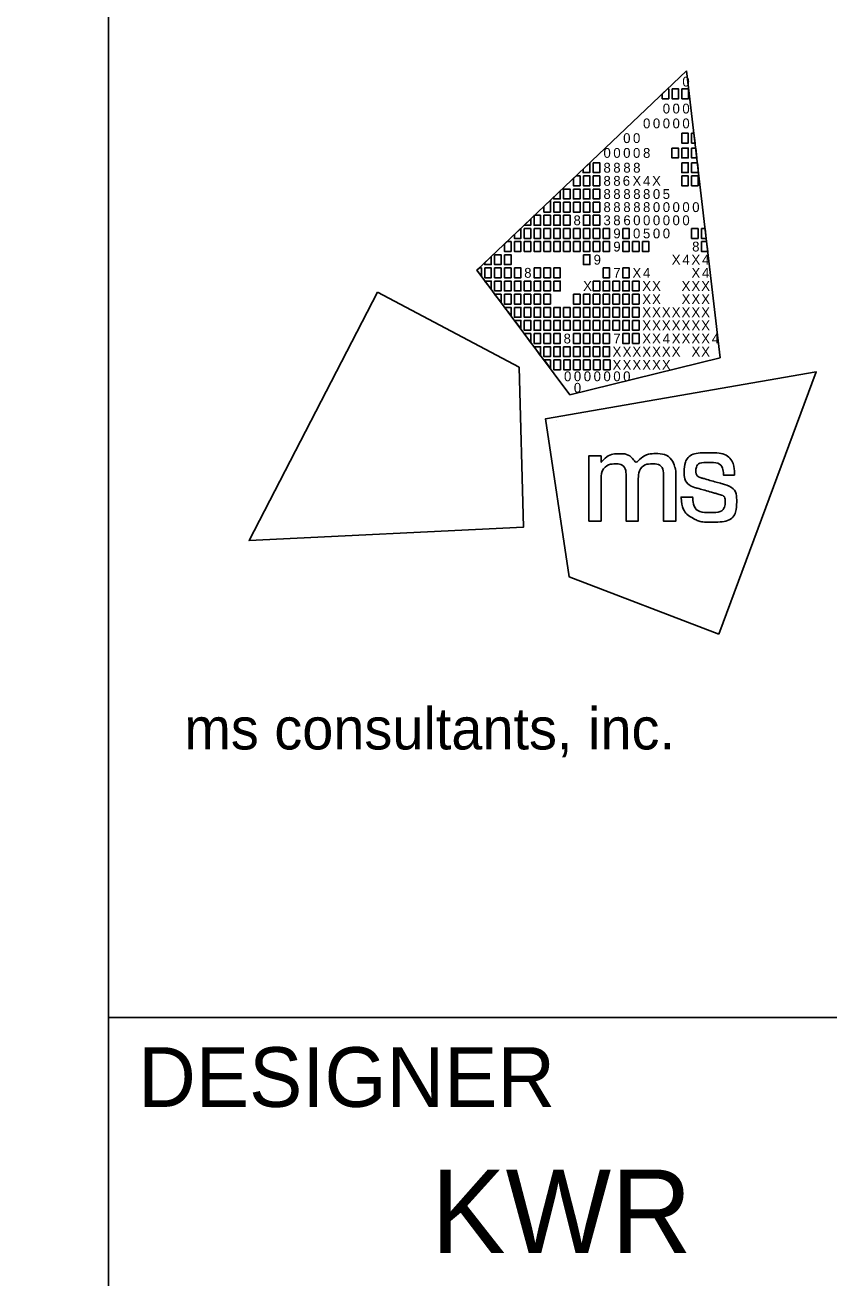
# Model space of a CAD drawing. Extents: x -0.2 to 34, y 0 to 22.
# Drawn here: x 31.86 to 33.207, y 2.063 to 4.163 of the extents above; entities that cross this region are included whole.
import ezdxf

# ---------------------------------------------------------------- set-up
doc = ezdxf.new("R2010")
doc.units = 0
for name, color, linetype in [('SC_Scratch1', 7, 'Continuous'), ('SH_Border', 7, 'Continuous'), ('SH_Data', 7, 'Continuous')]:
    doc.layers.add(name, color=color, linetype=linetype)

msp = doc.modelspace()

# ---------------------------------------------------------------- linework, layer by layer
at = {"layer": 'SC_Scratch1'}
msp.add_lwpolyline([(1.5, 21.5), (32, 21.5), (32, 0.5), (1.5, 0.5)], close=True, dxfattribs=at)
at = {"layer": 'SH_Border'}
for p, q in [((32, 0.5), (32, 21.5)), ((32, 2.5), (33.5, 2.5))]:
    msp.add_line(p, q, dxfattribs=at)
at = {"layer": 'SH_Data'}
for p, q in [((32.6175, 3.7519), (32.9688, 4.0861)), ((32.9688, 4.0861), (32.9688, 4.0861)), ((32.9688, 4.0861), (33.0253, 3.6052)), ((32.773, 3.543), (32.6175, 3.7519)), ((33.0253, 3.6052), (32.773, 3.543)), ((32.75, 3.5), (32.75, 3.5))]:
    msp.add_line(p, q, dxfattribs=at)
for points in [[(32.9279, 4.0472), (32.9369, 4.0558), (32.9389, 4.0558), (32.9389, 4.0393), (32.9279, 4.0393)], [(32.9444, 4.0558), (32.9554, 4.0558), (32.9554, 4.0393), (32.9444, 4.0393)], [(32.9609, 4.0558), (32.9719, 4.0558), (32.9719, 4.0393), (32.9609, 4.0393)], [(32.9606, 3.9815), (32.9716, 3.9815), (32.9716, 3.965), (32.9606, 3.965)], [(32.9771, 3.9815), (32.9811, 3.9815), (32.983, 3.965), (32.9771, 3.965)], [(32.9441, 3.9567), (32.9551, 3.9567), (32.9551, 3.9402), (32.9441, 3.9402)], [(32.9606, 3.9567), (32.9716, 3.9567), (32.9716, 3.9402), (32.9606, 3.9402)], [(32.9771, 3.9567), (32.984, 3.9567), (32.9859, 3.9402), (32.9771, 3.9402)], [(32.7953, 3.9211), (32.8064, 3.9316), (32.8064, 3.9154), (32.7953, 3.9154)], [(32.8123, 3.9319), (32.8233, 3.9319), (32.8233, 3.9154), (32.8123, 3.9154)], [(32.9606, 3.9319), (32.9716, 3.9319), (32.9716, 3.9154), (32.9606, 3.9154)], [(32.9771, 3.9319), (32.9869, 3.9319), (32.9881, 3.9218), (32.9881, 3.9154), (32.9771, 3.9154)], [(32.7958, 3.9099), (32.8068, 3.9099), (32.8068, 3.8934), (32.7958, 3.8934)], [(32.8123, 3.9099), (32.8233, 3.9099), (32.8233, 3.8934), (32.8123, 3.8934)], [(32.9606, 3.9099), (32.9716, 3.9099), (32.9716, 3.8934), (32.9606, 3.8934)], [(32.9771, 3.9099), (32.9881, 3.9099), (32.9881, 3.8934), (32.9771, 3.8934)], [(32.7627, 3.8879), (32.7737, 3.8879), (32.7737, 3.8714), (32.7627, 3.8714)], [(32.7793, 3.8879), (32.7903, 3.8879), (32.7903, 3.8714), (32.7793, 3.8714)], [(32.7958, 3.8879), (32.8068, 3.8879), (32.8068, 3.8714), (32.7958, 3.8714)], [(32.8123, 3.8879), (32.8233, 3.8879), (32.8233, 3.8714), (32.8123, 3.8714)], [(32.7462, 3.8659), (32.7572, 3.8659), (32.7572, 3.8494), (32.7462, 3.8494)], [(32.7627, 3.8659), (32.7737, 3.8659), (32.7737, 3.8494), (32.7627, 3.8494)], [(32.7793, 3.8659), (32.7903, 3.8659), (32.7903, 3.8494), (32.7793, 3.8494)], [(32.7958, 3.8659), (32.8068, 3.8659), (32.8068, 3.8494), (32.7958, 3.8494)], [(32.8123, 3.8659), (32.8233, 3.8659), (32.8233, 3.8494), (32.8123, 3.8494)], [(32.7297, 3.8439), (32.7407, 3.8439), (32.7407, 3.8273), (32.7297, 3.8273)], [(32.7462, 3.8439), (32.7572, 3.8439), (32.7572, 3.8273), (32.7462, 3.8273)], [(32.7627, 3.8439), (32.7737, 3.8439), (32.7737, 3.8273), (32.7627, 3.8273)], [(32.7958, 3.8439), (32.8068, 3.8439), (32.8068, 3.8273), (32.7958, 3.8273)], [(32.8123, 3.8439), (32.8233, 3.8439), (32.8233, 3.8273), (32.8123, 3.8273)], [(32.6967, 3.8218), (32.7077, 3.8218), (32.7077, 3.8053), (32.6967, 3.8053)], [(32.7132, 3.8218), (32.7242, 3.8218), (32.7242, 3.8053), (32.7132, 3.8053)], [(32.7297, 3.8218), (32.7407, 3.8218), (32.7407, 3.8053), (32.7297, 3.8053)], [(32.7462, 3.8218), (32.7572, 3.8218), (32.7572, 3.8053), (32.7462, 3.8053)], [(32.7627, 3.8218), (32.7737, 3.8218), (32.7737, 3.8053), (32.7627, 3.8053)], [(32.7793, 3.8218), (32.7903, 3.8218), (32.7903, 3.8053), (32.7793, 3.8053)], [(32.7958, 3.8218), (32.8068, 3.8218), (32.8068, 3.8053), (32.7958, 3.8053)], [(32.8123, 3.8218), (32.8233, 3.8218), (32.8233, 3.8053), (32.8123, 3.8053)], [(32.8288, 3.8218), (32.8398, 3.8218), (32.8398, 3.8053), (32.8288, 3.8053)], [(32.8618, 3.8218), (32.8728, 3.8218), (32.8728, 3.8053), (32.8618, 3.8053)], [(32.9771, 3.8218), (32.9881, 3.8218), (32.9881, 3.8053), (32.9771, 3.8053)], [(32.9935, 3.8218), (32.9998, 3.8218), (33.0018, 3.8053), (32.9935, 3.8053)], [(32.6802, 3.7998), (32.6912, 3.7998), (32.6912, 3.7833), (32.6802, 3.7833)], [(32.6967, 3.7998), (32.7077, 3.7998), (32.7077, 3.7833), (32.6967, 3.7833)], [(32.7132, 3.7998), (32.7242, 3.7998), (32.7242, 3.7833), (32.7132, 3.7833)], [(32.7297, 3.7998), (32.7407, 3.7998), (32.7407, 3.7833), (32.7297, 3.7833)], [(32.7462, 3.7998), (32.7572, 3.7998), (32.7572, 3.7833), (32.7462, 3.7833)], [(32.7627, 3.7998), (32.7737, 3.7998), (32.7737, 3.7833), (32.7627, 3.7833)], [(32.7793, 3.7998), (32.7903, 3.7998), (32.7903, 3.7833), (32.7793, 3.7833)], [(32.7958, 3.7998), (32.8068, 3.7998), (32.8068, 3.7833), (32.7958, 3.7833)], [(32.8123, 3.7998), (32.8233, 3.7998), (32.8233, 3.7833), (32.8123, 3.7833)], [(32.8288, 3.7998), (32.8398, 3.7998), (32.8398, 3.7833), (32.8288, 3.7833)], [(32.8618, 3.7998), (32.8728, 3.7998), (32.8728, 3.7833), (32.8618, 3.7833)], [(32.8783, 3.7998), (32.8893, 3.7998), (32.8893, 3.7833), (32.8783, 3.7833)], [(32.8947, 3.7998), (32.9057, 3.7998), (32.9057, 3.7833), (32.8947, 3.7833)], [(32.9935, 3.7998), (33.0024, 3.7998), (33.0044, 3.7833), (32.9935, 3.7833)], [(32.6471, 3.7778), (32.6581, 3.7778), (32.6581, 3.7613), (32.6471, 3.7613)], [(32.6637, 3.7778), (32.6747, 3.7778), (32.6747, 3.7613), (32.6637, 3.7613)], [(32.7958, 3.7778), (32.8068, 3.7778), (32.8068, 3.7613), (32.7958, 3.7613)], [(32.6306, 3.7558), (32.6416, 3.7558), (32.6416, 3.7393), (32.6306, 3.7393)], [(32.6471, 3.7558), (32.6581, 3.7558), (32.6581, 3.7393), (32.6471, 3.7393)], [(32.6637, 3.7558), (32.6747, 3.7558), (32.6747, 3.7393), (32.6637, 3.7393)], [(32.6802, 3.7558), (32.6912, 3.7558), (32.6912, 3.7393), (32.6802, 3.7393)], [(32.7132, 3.7558), (32.7242, 3.7558), (32.7242, 3.7393), (32.7132, 3.7393)], [(32.7297, 3.7558), (32.7407, 3.7558), (32.7407, 3.7393), (32.7297, 3.7393)], [(32.7462, 3.7558), (32.7572, 3.7558), (32.7572, 3.7393), (32.7462, 3.7393)], [(32.8288, 3.7558), (32.8398, 3.7558), (32.8398, 3.7393), (32.8288, 3.7393)], [(32.8618, 3.7558), (32.8728, 3.7558), (32.8728, 3.7393), (32.8618, 3.7393)], [(32.6306, 3.7338), (32.6416, 3.7338), (32.6416, 3.72)], [(32.6471, 3.7338), (32.6581, 3.7338), (32.6581, 3.7173), (32.6471, 3.7173)], [(32.6637, 3.7338), (32.6747, 3.7338), (32.6747, 3.7173), (32.6637, 3.7173)], [(32.6802, 3.7338), (32.6912, 3.7338), (32.6912, 3.7173), (32.6802, 3.7173)], [(32.6967, 3.7338), (32.7077, 3.7338), (32.7077, 3.7173), (32.6967, 3.7173)], [(32.7132, 3.7338), (32.7242, 3.7338), (32.7242, 3.7173), (32.7132, 3.7173)], [(32.7297, 3.7338), (32.7407, 3.7338), (32.7407, 3.7173), (32.7297, 3.7173)], [(32.7462, 3.7338), (32.7572, 3.7338), (32.7572, 3.7173), (32.7462, 3.7173)], [(32.8123, 3.7338), (32.8233, 3.7338), (32.8233, 3.7173), (32.8123, 3.7173)], [(32.8288, 3.7338), (32.8398, 3.7338), (32.8398, 3.7173), (32.8288, 3.7173)], [(32.8453, 3.7338), (32.8563, 3.7338), (32.8563, 3.7173), (32.8453, 3.7173)], [(32.8618, 3.7338), (32.8728, 3.7338), (32.8728, 3.7173), (32.8618, 3.7173)], [(32.8783, 3.7338), (32.8893, 3.7338), (32.8893, 3.7173), (32.8783, 3.7173)], [(32.6471, 3.7117), (32.6581, 3.7117), (32.6581, 3.698)], [(32.6637, 3.7117), (32.6747, 3.7117), (32.6747, 3.6952), (32.6637, 3.6952)], [(32.6802, 3.7117), (32.6912, 3.7117), (32.6912, 3.6952), (32.6802, 3.6952)], [(32.6967, 3.7117), (32.7077, 3.7117), (32.7077, 3.6952), (32.6967, 3.6952)], [(32.7132, 3.7117), (32.7242, 3.7117), (32.7242, 3.6952), (32.7132, 3.6952)], [(32.7297, 3.7117), (32.7407, 3.7117), (32.7407, 3.6952), (32.7297, 3.6952)], [(32.7793, 3.7117), (32.7903, 3.7117), (32.7903, 3.6952), (32.7793, 3.6952)], [(32.7958, 3.7117), (32.8068, 3.7117), (32.8068, 3.6952), (32.7958, 3.6952)], [(32.8123, 3.7117), (32.8233, 3.7117), (32.8233, 3.6952), (32.8123, 3.6952)], [(32.8288, 3.7117), (32.8398, 3.7117), (32.8398, 3.6952), (32.8288, 3.6952)], [(32.8453, 3.7117), (32.8563, 3.7117), (32.8563, 3.6952), (32.8453, 3.6952)], [(32.8618, 3.7117), (32.8728, 3.7117), (32.8728, 3.6952), (32.8618, 3.6952)], [(32.8783, 3.7117), (32.8893, 3.7117), (32.8893, 3.6952), (32.8783, 3.6952)], [(32.6637, 3.6897), (32.6747, 3.6897), (32.6747, 3.676)], [(32.6747, 3.6897), (32.6747, 3.6897), (32.6747, 3.6897)], [(32.6802, 3.6897), (32.6912, 3.6897), (32.6912, 3.6732), (32.6802, 3.6732)], [(32.6967, 3.6897), (32.7077, 3.6897), (32.7077, 3.6732), (32.6967, 3.6732)], [(32.7132, 3.6897), (32.7242, 3.6897), (32.7242, 3.6732), (32.7132, 3.6732)], [(32.7297, 3.6897), (32.7407, 3.6897), (32.7407, 3.6732), (32.7297, 3.6732)], [(32.7462, 3.6897), (32.7572, 3.6897), (32.7572, 3.6732), (32.7462, 3.6732)], [(32.7627, 3.6897), (32.7737, 3.6897), (32.7737, 3.6732), (32.7627, 3.6732)], [(32.7793, 3.6897), (32.7903, 3.6897), (32.7903, 3.6732), (32.7793, 3.6732)], [(32.7958, 3.6897), (32.8068, 3.6897), (32.8068, 3.6732), (32.7958, 3.6732)], [(32.8123, 3.6897), (32.8233, 3.6897), (32.8233, 3.6732), (32.8123, 3.6732)], [(32.8288, 3.6897), (32.8398, 3.6897), (32.8398, 3.6732), (32.8288, 3.6732)], [(32.8453, 3.6897), (32.8563, 3.6897), (32.8563, 3.6732), (32.8453, 3.6732)], [(32.8618, 3.6897), (32.8728, 3.6897), (32.8728, 3.6732), (32.8618, 3.6732)], [(32.8783, 3.6897), (32.8893, 3.6897), (32.8893, 3.6732), (32.8783, 3.6732)], [(32.6802, 3.6677), (32.6912, 3.6677), (32.6912, 3.654)], [(32.6967, 3.6677), (32.7077, 3.6677), (32.7077, 3.6512), (32.6967, 3.6512)], [(32.7132, 3.6677), (32.7242, 3.6677), (32.7242, 3.6512), (32.7132, 3.6512)], [(32.7297, 3.6677), (32.7407, 3.6677), (32.7407, 3.6512), (32.7297, 3.6512)], [(32.7462, 3.6677), (32.7572, 3.6677), (32.7572, 3.6512), (32.7462, 3.6512)], [(32.7627, 3.6677), (32.7737, 3.6677), (32.7737, 3.6512), (32.7627, 3.6512)], [(32.7793, 3.6677), (32.7903, 3.6677), (32.7903, 3.6512), (32.7793, 3.6512)], [(32.7958, 3.6677), (32.8068, 3.6677), (32.8068, 3.6512), (32.7958, 3.6512)], [(32.8123, 3.6677), (32.8233, 3.6677), (32.8233, 3.6512), (32.8123, 3.6512)], [(32.8288, 3.6677), (32.8398, 3.6677), (32.8398, 3.6512), (32.8288, 3.6512)], [(32.8453, 3.6677), (32.8563, 3.6677), (32.8563, 3.6512), (32.8453, 3.6512)], [(32.8618, 3.6677), (32.8728, 3.6677), (32.8728, 3.6512), (32.8618, 3.6512)], [(32.8783, 3.6677), (32.8893, 3.6677), (32.8893, 3.6512), (32.8783, 3.6512)], [(32.7077, 3.6305), (32.6965, 3.6457), (32.7077, 3.6457)], [(32.7132, 3.6457), (32.7242, 3.6457), (32.7242, 3.6292), (32.7132, 3.6292)], [(32.7297, 3.6457), (32.7407, 3.6457), (32.7407, 3.6292), (32.7297, 3.6292)], [(32.7462, 3.6457), (32.7572, 3.6457), (32.7572, 3.6292), (32.7462, 3.6292)], [(32.7793, 3.6457), (32.7903, 3.6457), (32.7903, 3.6292), (32.7793, 3.6292)], [(32.7958, 3.6457), (32.8068, 3.6457), (32.8068, 3.6292), (32.7958, 3.6292)], [(32.8123, 3.6457), (32.8233, 3.6457), (32.8233, 3.6292), (32.8123, 3.6292)], [(32.8288, 3.6457), (32.8398, 3.6457), (32.8398, 3.6292), (32.8288, 3.6292)], [(32.8618, 3.6457), (32.8728, 3.6457), (32.8728, 3.6292), (32.8618, 3.6292)], [(32.8783, 3.6457), (32.8893, 3.6457), (32.8893, 3.6292), (32.8783, 3.6292)], [(32.724, 3.6082), (32.7132, 3.6237), (32.7242, 3.6237)], [(32.7297, 3.6237), (32.7407, 3.6237), (32.7407, 3.6072), (32.7297, 3.6072)], [(32.7462, 3.6237), (32.7572, 3.6237), (32.7572, 3.6072), (32.7462, 3.6072)], [(32.7627, 3.6237), (32.7737, 3.6237), (32.7737, 3.6072), (32.7627, 3.6072)], [(32.7793, 3.6237), (32.7903, 3.6237), (32.7903, 3.6072), (32.7793, 3.6072)], [(32.7958, 3.6237), (32.8068, 3.6237), (32.8068, 3.6072), (32.7958, 3.6072)], [(32.8123, 3.6237), (32.8233, 3.6237), (32.8233, 3.6072), (32.8123, 3.6072)], [(32.8288, 3.6237), (32.8398, 3.6237), (32.8398, 3.6072), (32.8288, 3.6072)], [(32.7302, 3.6017), (32.7407, 3.6017), (32.7408, 3.5875)], [(32.7463, 3.6017), (32.7573, 3.6017), (32.7573, 3.5852), (32.7463, 3.5852)], [(32.763, 3.6017), (32.774, 3.6017), (32.774, 3.5852), (32.763, 3.5852)], [(32.7794, 3.6017), (32.7904, 3.6017), (32.7904, 3.5852), (32.7794, 3.5852)], [(32.796, 3.6017), (32.807, 3.6017), (32.807, 3.5852), (32.796, 3.5852)], [(32.8129, 3.6017), (32.8239, 3.6017), (32.8239, 3.5851), (32.8129, 3.5851)], [(32.8296, 3.6017), (32.8406, 3.6017), (32.8406, 3.5851), (32.8296, 3.5851)]]:
    msp.add_lwpolyline(points, close=True, dxfattribs=at)
for points in [[(32.7903, 3.9099), (32.7836, 3.9099), (32.7793, 3.9058), (32.7793, 3.8934), (32.7903, 3.8934), (32.7903, 3.9099)], [(32.7572, 3.8849), (32.7462, 3.8744), (32.7462, 3.8714), (32.7572, 3.8714), (32.7572, 3.8849)], [(32.7407, 3.8691), (32.7297, 3.8587), (32.7297, 3.8494), (32.7407, 3.8494), (32.7407, 3.8691)], [(32.7242, 3.8439), (32.7141, 3.8439), (32.7132, 3.843), (32.7132, 3.8273), (32.7242, 3.8273), (32.7242, 3.8439)], [(32.6912, 3.822), (32.6802, 3.8115), (32.6802, 3.8053), (32.6912, 3.8053), (32.6912, 3.822)], [(32.7077, 3.8377), (32.6968, 3.8273), (32.7077, 3.8273), (32.7077, 3.8377)], [(32.6747, 3.7998), (32.6679, 3.7998), (32.6637, 3.7958), (32.6637, 3.7833), (32.6747, 3.7833), (32.6747, 3.7998)], [(32.6416, 3.7749), (32.6306, 3.7644), (32.6306, 3.7613), (32.6416, 3.7613), (32.6416, 3.7749)], [(32.6251, 3.7558), (32.6216, 3.7558), (32.6175, 3.7519), (32.6251, 3.7417), (32.6251, 3.7558)], [(32.4512, 3.7149), (32.2359, 3.2988), (32.6956, 3.3215), (32.6884, 3.5892), (32.4512, 3.7149)], [(33.0229, 3.1422), (33.1859, 3.5814), (32.7324, 3.5029), (32.7722, 3.2381), (33.0229, 3.1422)]]:
    msp.add_lwpolyline(points, dxfattribs=at)
for points in [[(32.8048, 3.3315), (32.8048, 3.3315), (32.8048, 3.4409), (32.8048, 3.4409), (32.8048, 3.4409), (32.8255, 3.4409), (32.8255, 3.4409), (32.8255, 3.4409), (32.8255, 3.4297), (32.8255, 3.4297), (32.8346, 3.4399), (32.8457, 3.4445), (32.8555, 3.4445), (32.8688, 3.4445), (32.8791, 3.4372), (32.8837, 3.4266), (32.8915, 3.4381), (32.905, 3.4446), (32.9166, 3.4446), (32.9325, 3.4446), (32.9451, 3.435), (32.9494, 3.4213), (32.9494, 3.4212), (32.9494, 3.4212), (32.9494, 3.4212), (32.9501, 3.419), (32.9506, 3.4172), (32.9506, 3.4071), (32.9506, 3.4071), (32.9506, 3.3314), (32.9506, 3.3314), (32.9506, 3.3314), (32.9303, 3.3314), (32.9303, 3.3314), (32.9303, 3.3314), (32.9303, 3.4048), (32.9303, 3.4048), (32.9303, 3.4201), (32.9219, 3.4274), (32.911, 3.4274), (32.8995, 3.4274), (32.8879, 3.4171), (32.8879, 3.4001), (32.8879, 3.4001), (32.8879, 3.3315), (32.8879, 3.3315), (32.8879, 3.3315), (32.8674, 3.3315), (32.8674, 3.3315), (32.8674, 3.3315), (32.8674, 3.4059), (32.8674, 3.4059), (32.8674, 3.4203), (32.8588, 3.4274), (32.8496, 3.4274), (32.8384, 3.4274), (32.8254, 3.417), (32.8254, 3.3962), (32.8254, 3.3962), (32.8254, 3.3315), (32.8254, 3.3315), (32.8254, 3.3315), (32.8048, 3.3315), (32.8048, 3.3315)], [(32.9595, 3.3709), (32.9595, 3.3709), (32.9595, 3.3717), (32.9595, 3.3717), (32.9595, 3.3717), (32.9603, 3.3717), (32.9603, 3.3717), (32.9603, 3.3717), (32.9783, 3.3717), (32.9783, 3.3717), (32.9783, 3.3717), (32.9789, 3.3717), (32.9789, 3.3717), (32.9789, 3.3717), (32.979, 3.371), (32.979, 3.371), (32.9803, 3.3554), (32.9887, 3.346), (33.009, 3.346), (33.0273, 3.346), (33.0333, 3.3554), (33.0333, 3.3631), (33.0333, 3.3732), (33.0256, 3.3758), (33.0175, 3.378), (33.0175, 3.378), (32.987, 3.3867), (32.987, 3.3867), (32.972, 3.3909), (32.9648, 3.4019), (32.9648, 3.4142), (32.9648, 3.4303), (32.9768, 3.4462), (33.0052, 3.4462), (33.0348, 3.4462), (33.0489, 3.4285), (33.0489, 3.4095), (33.0489, 3.4095), (33.0489, 3.4087), (33.0489, 3.4087), (33.0489, 3.4087), (33.0482, 3.4087), (33.0482, 3.4087), (33.0482, 3.4087), (33.0312, 3.4087), (33.0312, 3.4087), (33.0312, 3.4087), (33.0305, 3.4087), (33.0305, 3.4087), (33.0305, 3.4087), (33.0305, 3.4094), (33.0305, 3.4094), (33.0301, 3.4208), (33.0226, 3.43), (33.0056, 3.43), (32.9891, 3.43), (32.9843, 3.4218), (32.9843, 3.4157), (32.9843, 3.4108), (32.9869, 3.4059), (32.9959, 3.4033), (32.9959, 3.4033), (33.0255, 3.3948), (33.0255, 3.3948), (33.0462, 3.3889), (33.0527, 3.3777), (33.0527, 3.3639), (33.0527, 3.3462), (33.041, 3.3298), (33.0087, 3.3298), (32.9952, 3.3298), (32.9877, 3.3321), (32.9823, 3.3348), (32.969, 3.3414), (32.9609, 3.3536), (32.9595, 3.3709)]]:
    msp.add_open_spline(points, degree=3, dxfattribs=at)

# ---------------------------------------------------------------- texts
for s, height, p in [('0', 0.0165, (32.9617, 4.0597)), ('0', 0.0165, (32.9288, 4.0145)), ('0', 0.0165, (32.9452, 4.0145)), ('0', 0.0165, (32.9617, 4.0145)), ('0', 0.0165, (32.8958, 3.9897)), ('0', 0.0165, (32.9123, 3.9897)), ('0', 0.0165, (32.9288, 3.9897)), ('0', 0.0165, (32.9452, 3.9897)), ('0', 0.0165, (32.9617, 3.9897)), ('0', 0.0165, (32.8625, 3.965)), ('0', 0.0165, (32.879, 3.965)), ('0', 0.0165, (32.8295, 3.9402)), ('0', 0.0165, (32.846, 3.9402)), ('0', 0.0165, (32.8625, 3.9402)), ('0', 0.0165, (32.879, 3.9402)), ('8', 0.0165, (32.8958, 3.9402)), ('8', 0.0165, (32.8295, 3.9154)), ('8', 0.0165, (32.846, 3.9154)), ('8', 0.0165, (32.8628, 3.9154)), ('8', 0.0165, (32.8793, 3.9154)), ('8', 0.0165, (32.8295, 3.8934)), ('8', 0.0165, (32.846, 3.8934)), ('6', 0.0165, (32.8618, 3.8934)), ('X', 0.0165, (32.8781, 3.8934)), ('4', 0.0165, (32.8958, 3.8934)), ('X', 0.0165, (32.911, 3.8934)), ('8', 0.0165, (32.8295, 3.8713)), ('8', 0.0165, (32.846, 3.8713)), ('8', 0.0165, (32.8628, 3.8713)), ('8', 0.0165, (32.8794, 3.8713)), ('8', 0.0165, (32.8958, 3.8713)), ('0', 0.0165, (32.9123, 3.8713)), ('5', 0.0165, (32.9287, 3.8713)), ('8', 0.0165, (32.8295, 3.8494)), ('8', 0.0165, (32.846, 3.8494)), ('8', 0.0165, (32.8628, 3.8494)), ('8', 0.0165, (32.8794, 3.8494)), ('8', 0.0165, (32.8958, 3.8494)), ('0', 0.0165, (32.9123, 3.8494)), ('0', 0.0165, (32.9288, 3.8494)), ('0', 0.0165, (32.9452, 3.8494)), ('0', 0.0165, (32.9617, 3.8494)), ('0', 0.0165, (32.9782, 3.8494)), ('8', 0.0165, (32.7793, 3.8273)), ('3', 0.0165, (32.8295, 3.8273)), ('8', 0.0165, (32.846, 3.8273)), ('6', 0.0165, (32.8629, 3.8273)), ('0', 0.0165, (32.8793, 3.8273)), ('0', 0.0165, (32.8958, 3.8273)), ('0', 0.0165, (32.9123, 3.8273)), ('0', 0.0165, (32.9288, 3.8273)), ('0', 0.0165, (32.9452, 3.8273)), ('0', 0.0165, (32.9617, 3.8273)), ('9', 0.0165, (32.846, 3.8053)), ('0', 0.0165, (32.879, 3.8053)), ('5', 0.0165, (32.8957, 3.8053)), ('0', 0.0165, (32.9123, 3.8053)), ('0', 0.0165, (32.9288, 3.8053)), ('9', 0.0165, (32.846, 3.7833)), ('8', 0.0165, (32.9781, 3.7833)), ('9', 0.0165, (32.813, 3.7613)), ('X', 0.0165, (32.9439, 3.7613)), ('4', 0.0165, (32.9617, 3.7613)), ('X', 0.0165, (32.9769, 3.7613)), ('4', 0.0165, (32.9946, 3.7613)), ('8', 0.0165, (32.6967, 3.7393)), ('7', 0.0165, (32.846, 3.7393)), ('X', 0.0165, (32.8781, 3.7393)), ('4', 0.0165, (32.8958, 3.7393)), ('X', 0.0165, (32.9769, 3.7393)), ('4', 0.0165, (32.9946, 3.7393)), ('X', 0.0165, (32.7955, 3.7173)), ('X', 0.0165, (32.8945, 3.7173)), ('X', 0.0165, (32.911, 3.7173)), ('X', 0.0165, (32.9604, 3.7173)), ('X', 0.0165, (32.9769, 3.7173)), ('X', 0.0165, (32.9933, 3.7173)), ('X', 0.0165, (32.8945, 3.6952)), ('X', 0.0165, (32.911, 3.6952)), ('X', 0.0165, (32.9604, 3.6952)), ('X', 0.0165, (32.9769, 3.6952)), ('X', 0.0165, (32.9933, 3.6952)), ('X', 0.0165, (32.8945, 3.6732)), ('X', 0.0165, (32.911, 3.6732)), ('X', 0.0165, (32.9274, 3.6732)), ('X', 0.0165, (32.9439, 3.6732)), ('X', 0.0165, (32.9604, 3.6732)), ('X', 0.0165, (32.9769, 3.6732)), ('X', 0.0165, (32.9933, 3.6732)), ('X', 0.0165, (32.8945, 3.6512)), ('X', 0.0165, (32.911, 3.6512)), ('X', 0.0165, (32.9274, 3.6512)), ('X', 0.0165, (32.9439, 3.6512)), ('X', 0.0165, (32.9604, 3.6512)), ('X', 0.0165, (32.9769, 3.6512)), ('X', 0.0165, (32.9933, 3.6512)), ('8', 0.0165, (32.7627, 3.6292)), ('7', 0.0165, (32.846, 3.6292)), ('X', 0.0165, (32.8945, 3.6292)), ('X', 0.0165, (32.911, 3.6292)), ('4', 0.0165, (32.9288, 3.6292)), ('X', 0.0165, (32.9439, 3.6292)), ('X', 0.0165, (32.9604, 3.6292)), ('X', 0.0165, (32.9769, 3.6292)), ('X', 0.0165, (32.9933, 3.6292)), ('4', 0.0165, (33.0111, 3.6292)), ('X', 0.0165, (32.8447, 3.6072)), ('X', 0.0165, (32.8616, 3.6072)), ('X', 0.0165, (32.878, 3.6072)), ('X', 0.0165, (32.8945, 3.6072)), ('X', 0.0165, (32.911, 3.6072)), ('X', 0.0165, (32.9274, 3.6072)), ('X', 0.0165, (32.9439, 3.6072)), ('X', 0.0165, (32.9771, 3.6072)), ('X', 0.0165, (32.9933, 3.6072)), ('X', 0.0165, (32.8447, 3.5851)), ('X', 0.0165, (32.8616, 3.5851)), ('X', 0.0165, (32.878, 3.5851)), ('X', 0.0165, (32.8945, 3.5851)), ('X', 0.0165, (32.911, 3.5851)), ('X', 0.0165, (32.9274, 3.5851)), ('0', 0.0165, (32.7634, 3.5659)), ('0', 0.0165, (32.7799, 3.5659)), ('0', 0.0165, (32.7965, 3.5659)), ('0', 0.0165, (32.813, 3.5659)), ('0', 0.0165, (32.8295, 3.5659)), ('0', 0.0165, (32.846, 3.5659)), ('0', 0.0165, (32.8625, 3.5659)), ('0', 0.0165, (32.7799, 3.5467)), ('ms consultants, inc.', 0.07, (32.1273, 2.9489))]:
    msp.add_text(s, height=height, rotation=360, dxfattribs=at).set_placement(p)
for s, height, p in [('DESIGNER', 0.1, (32.05, 2.35)), ('KWR', 0.14, (32.5407, 2.105))]:
    msp.add_text(s, height=height, dxfattribs=at).set_placement(p)

doc.saveas('drawing.dxf')
